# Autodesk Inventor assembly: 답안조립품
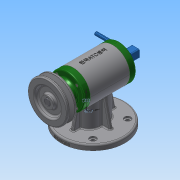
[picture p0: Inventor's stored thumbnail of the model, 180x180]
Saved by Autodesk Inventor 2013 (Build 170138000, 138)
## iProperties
Created: 2017-02
Part Number: 답안조립품
Document SubType Name: Assembly
Designer: Administrator
Mass: 1347.69 g
Surface Area: 1453.46 cm^2
Volume: 463.015 cm^3
Density: 2.91067 g/cm^3
Author: Administrator
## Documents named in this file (16)
- C:\Users\Administrator\Desktop\370208V1023\답안조립품.iam
- C:\Users\Administrator\Desktop\370208V1023\본체.ipt
- C:\Users\Administrator\Desktop\370208V1023\멈춤나사 M3x8.ipt
- C:\Users\Administrator\Desktop\370208V1023\키 4 x 4 x 18.ipt
- C:\Users\Administrator\Desktop\370208V1023\편심축.ipt
- C:\Users\Administrator\Desktop\370208V1023\베어링 6201.ipt
- C:\Users\Administrator\Desktop\370208V1023\앞커버.ipt
- C:\Users\Administrator\Desktop\370208V1023\오일실 12 22 7.ipt
- C:\Users\Administrator\Desktop\370208V1023\볼트 M3x0.5x8.ipt
- C:\Users\Administrator\Desktop\370208V1023\V벨트풀리.ipt
- C:\Users\Administrator\Desktop\370208V1023\베어링 6202.ipt
- C:\Users\Administrator\Desktop\370208V1023\뒤커버.ipt
- C:\Users\Administrator\Desktop\370208V1023\레버.ipt
- C:\Users\Administrator\Desktop\370208V1023\가변스프링.ipt
- C:\Users\Administrator\Desktop\370208V1023\슬라이드.ipt
- C:\Users\Administrator\Desktop\370208V1023\본체상부커버.ipt
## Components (2 placed, 2 different names)
1. V벨트풀리:1
2. 가변스프링:1
